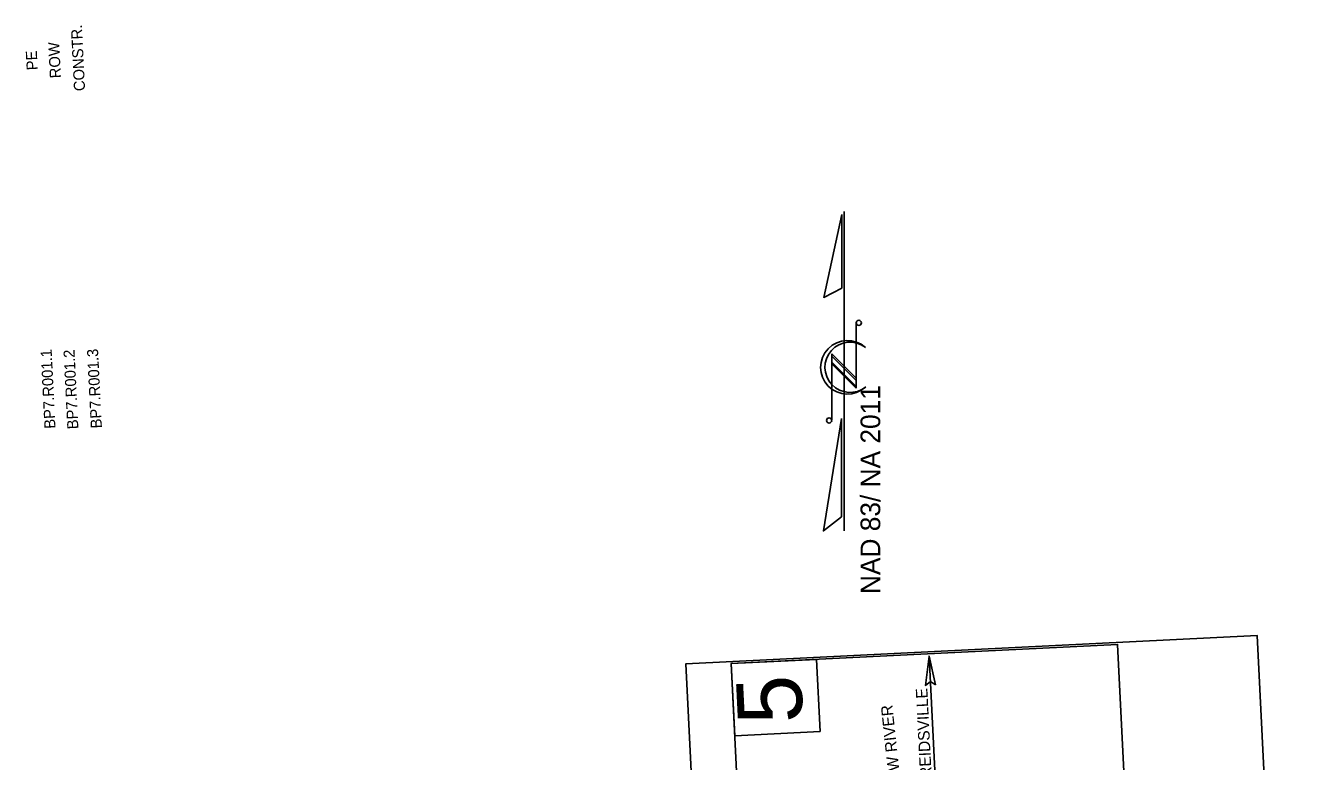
# Model space of a CAD drawing. Extents: x 1805231 to 1809482, y 908883 to 918297.
# Drawn here: x 1805231 to 1808728, y 916301 to 918297 of the extents above; entities that cross this region are included whole.
import ezdxf

# ---------------------------------------------------------------- set-up
doc = ezdxf.new("R2010")
doc.units = 0
for name, color, linetype in [('Old_Level_40', 7, 'Continuous'), ('Prop Horizontal Alignment Station Label', 7, 'Continuous'), ('Prop Leader Line Medium', 7, 'Continuous'), ('Prop Shade Medium', 7, 'Continuous'), ('Prop Terminator CELL', 7, 'Continuous'), ('Scratch_Level_0', 7, 'Continuous'), ('Sheet North Arrow CELL', 7, 'Continuous')]:
    doc.layers.add(name, color=color, linetype=linetype)

msp = doc.modelspace()

# ---------------------------------------------------------------- linework, layer by layer
at = {"layer": 'Prop Leader Line Medium'}
msp.add_line((1807681.3, 916586.7), (1807700.8, 916193.6), dxfattribs=at)
at = {"layer": 'Prop Shade Medium'}
for points in [[(1808257.3, 915314.8), (1808192.5, 916618.4), (1807143.8, 916566.3), (1807143.8, 916566.3), (1807144.4, 916566.4), (1807218.2, 915068.2), (1807212.6, 915181), (1807444, 915192.5)], [(1807144.4, 916566.4), (1807154.1, 916370.7), (1807385.5, 916382.2), (1807375.7, 916577.9)]]:
    msp.add_lwpolyline(points, close=True, dxfattribs=at)
at = {"layer": 'Prop Terminator CELL'}
msp.add_lwpolyline([(1807698.8, 916508.8), (1807681.3, 916586.7), (1807671.2, 916507), (1807684.7, 916517.7)], close=True, dxfattribs=at)
at = {"layer": 'Scratch_Level_0'}
msp.add_lwpolyline([(1807178.4, 913396.6), (1807021.1, 916565.5), (1808571, 916642.5), (1808728.3, 913473.6)], close=True, dxfattribs=at)
at = {"layer": 'Sheet North Arrow CELL'}
for p, q in [((1807450.6, 916926.3), (1807450.6, 917793)), ((1807483.3, 917491.4), (1807483.3, 917313.5)), ((1807507.8, 917425.1), (1807508.8, 917424.4)), ((1807483.3, 917341.2), (1807417, 917407.5)), ((1807417, 917407.5), (1807417, 917226.7)), ((1807483.3, 917334.7), (1807417, 917401)), ((1807417, 917401), (1807417, 917384.7)), ((1807483.3, 917318.4), (1807417, 917384.7)), ((1807417, 917384.7), (1807483.3, 917318.4)), ((1807483.3, 917313.5), (1807417, 917379.8)), ((1807483.3, 917318.4), (1807483.3, 917334.7))]:
    msp.add_line(p, q, dxfattribs=at)
for points in [[(1807444.6, 917785.4), (1807395.2, 917560.3), (1807444.6, 917585.4)], [(1807443.6, 917231.6), (1807394.5, 916926.3), (1807443.6, 916965)]]:
    msp.add_lwpolyline(points, close=True, dxfattribs=at)
for centre in [(1807490.4, 917491.2), (1807410, 917226.4)]:
    msp.add_circle(centre, 7.07, dxfattribs=at)
for centre, radius, start, end in [((1807459.8, 917370.5), 72.8, 47.84, 312.3941), ((1807466.9, 917370.5), 68.2, 53.095, 308.6287)]:
    msp.add_arc(centre, radius, start, end, dxfattribs=at)

# ---------------------------------------------------------------- texts
at = {"layer": 'Old_Level_40'}
for s, p in [('CONSTR.', (1805392.3, 918120.8)), ('PE', (1805263.7, 918177.5)), ('ROW', (1805326.7, 918155.7)), ('BP7.R001.1', (1805312, 917204.5)), ('BP7.R001.2', (1805374, 917203.2)), ('BP7.R001.3', (1805437.8, 917205.4))]:
    msp.add_text(s, height=30, rotation=92.8422, dxfattribs=at).set_placement(p)
at = {"layer": 'Prop Horizontal Alignment Station Label'}
msp.add_text('HAW RIVER', height=31.5, rotation=96.0539, dxfattribs=at).set_placement((1807606.6, 916218.3))
at = {"layer": 'Prop Leader Line Medium'}
msp.add_text('TO REIDSVILLE', height=31.5, rotation=92.8385, dxfattribs=at).set_placement((1807691.8, 916187))
at = {"layer": 'Prop Shade Medium'}
msp.add_text('5', height=176.6, rotation=92.8422, dxfattribs=at).set_placement((1807339.6, 916407.4))
at = {"layer": 'Sheet North Arrow CELL'}
msp.add_text('         NAD 83/ NA 2011', height=53.334, rotation=90, dxfattribs=at).set_placement((1807548.6, 916576.9))

doc.saveas('drawing.dxf')
